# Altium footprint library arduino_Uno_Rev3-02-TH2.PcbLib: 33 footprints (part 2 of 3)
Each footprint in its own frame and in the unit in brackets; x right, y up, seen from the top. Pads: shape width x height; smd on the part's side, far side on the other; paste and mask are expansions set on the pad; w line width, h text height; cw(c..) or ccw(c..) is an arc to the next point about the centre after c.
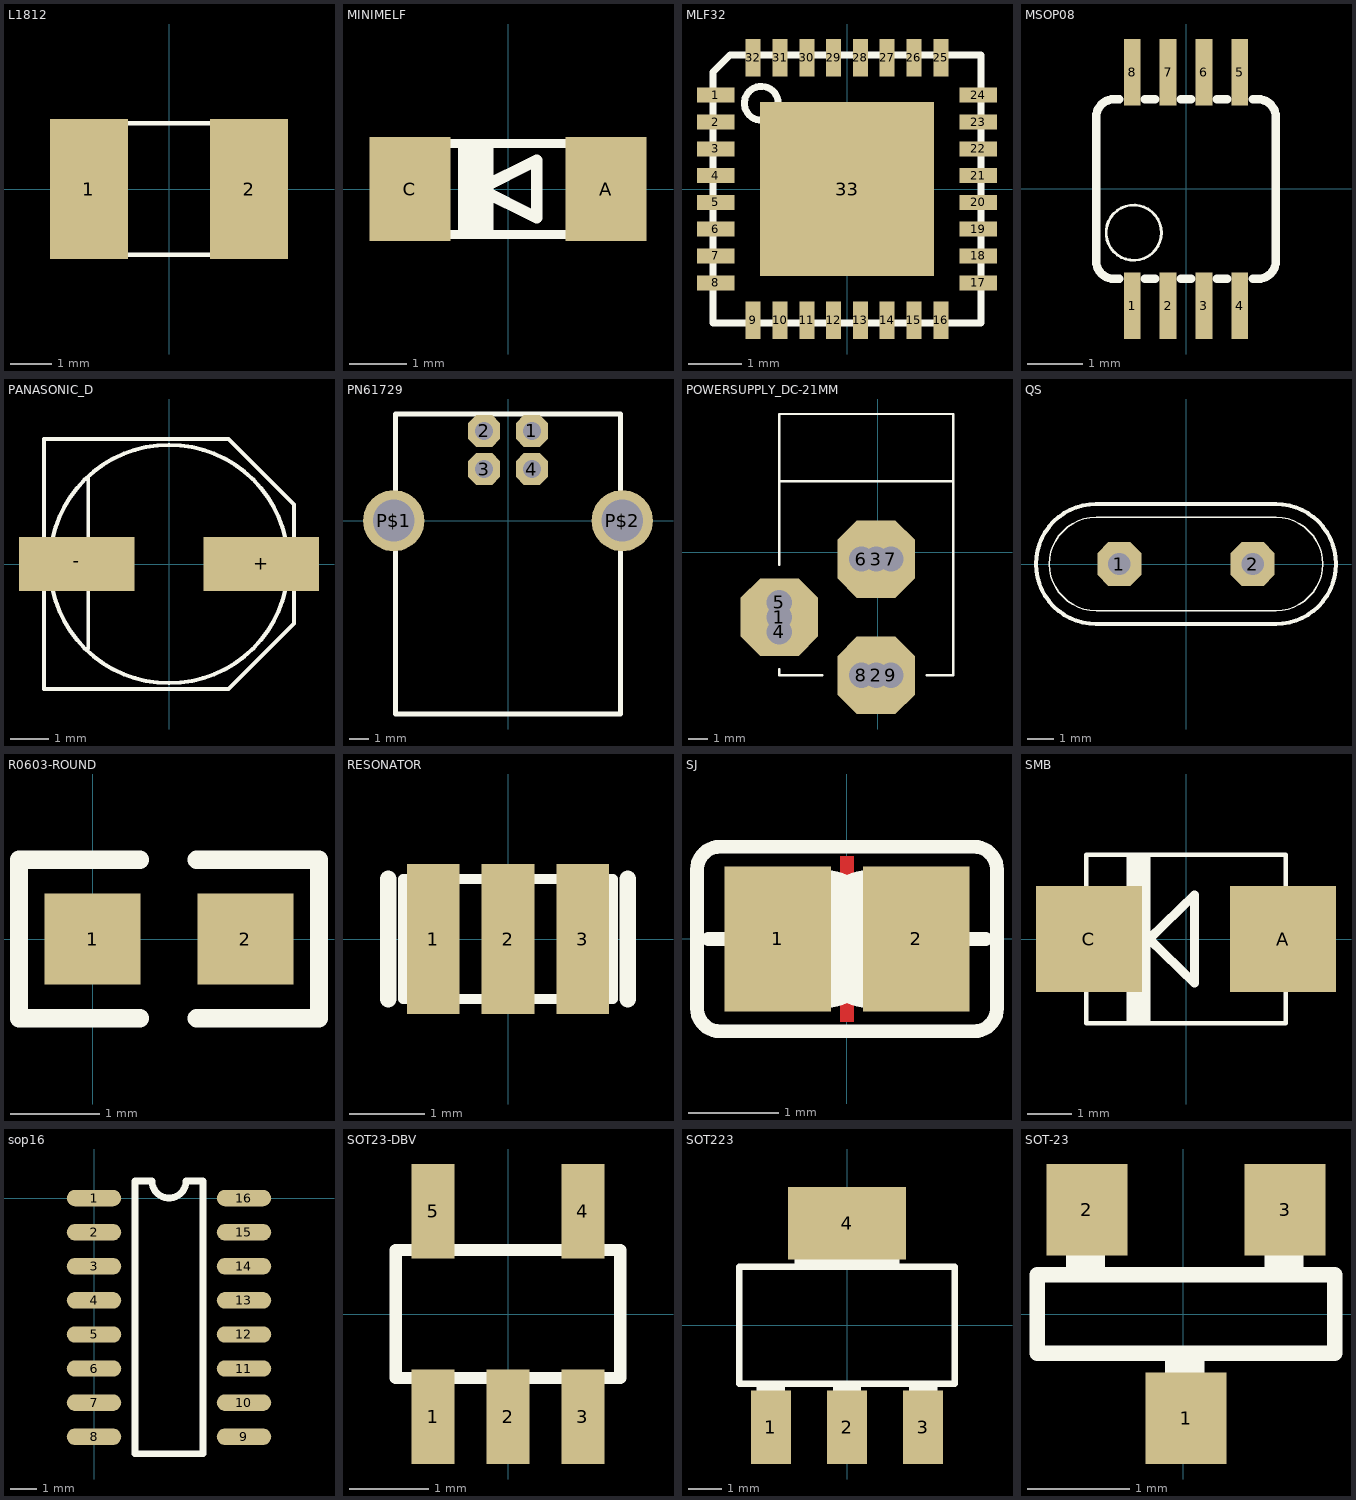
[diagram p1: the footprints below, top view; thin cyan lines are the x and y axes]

## L1812 [mm]
pads (2):
  rect 1.9x3.4 smd: 1(-1.95,0) 2(1.95,0)
Top Overlay:
  rectangle: -2.388,-1.651 -1.438,1.649
  rectangle: 1.448,-1.651 2.398,1.649
  lines w0.102: -1.473,1.6 1.473,1.6 ; -1.448,-1.6 1.473,-1.6

## MINIMELF [mm]
pads (2):
  rect 1.4x1.8 smd: A(1.7,0) C(-1.7,0)
Top Overlay:
  rectangle: -0.864,-0.787 -0.254,0.787
  rectangle: 1.295,-0.864 1.854,0.864
  rectangle: -1.854,-0.864 -1.295,0.864
  lines w0.152: -1.321,-0.787 1.321,-0.787 ; -1.321,0.787 1.321,0.787
  lines w0.203: -0.5,0 0.5,-0.5 0.5,0.5 -0.5,0

## MLF32 [mm]
pads (33):
  rect 0.7x0.28 smd: 1(-2.45,1.75) 2(-2.45,1.25) 3(-2.45,0.75) 4(-2.45,0.25) 5(-2.45,-0.25) 6(-2.45,-0.75) 7(-2.45,-1.25) 8(-2.45,-1.75) 17(2.45,-1.75) 18(2.45,-1.25) 19(2.45,-0.75) 20(2.45,-0.25) 21(2.45,0.25) 22(2.45,0.75) 23(2.45,1.25) 24(2.45,1.75)
  rect 0.28x0.7 smd: 9(-1.75,-2.45) 10(-1.25,-2.45) 11(-0.75,-2.45) 12(-0.25,-2.45) 13(0.25,-2.45) 14(0.75,-2.45) 15(1.25,-2.45) 16(1.75,-2.45) 25(1.75,2.45) 26(1.25,2.45) 27(0.75,2.45) 28(0.25,2.45) 29(-0.25,2.45) 30(-0.75,2.45) 31(-1.25,2.45) 32(-1.75,2.45)
  rect 3.254x3.254 smd: 33(0,0)
Top Layer:
  rectangle: -0.635,-0.635 0.635,0.635
Top Overlay:
  circle w0.127: c-1.6,1.6 r0.316
  lines w0.127: -2.5,-2.5 -2.5,2.183 -2.183,2.5 2.5,2.5 2.5,-2.5 -2.5,-2.5

## MSOP08 [mm]
pads (8):
  rect 0.3x1.2 smd: 1(-0.976,-2.113) 2(-0.326,-2.113) 3(0.324,-2.113) 4(0.974,-2.113) 5(0.974,2.112) 6(0.324,2.112) 7(-0.326,2.112) 8(-0.976,2.112)
Top Overlay:
  circle w0.051: c-0.946,-0.791 r0.5
  rectangle: -1.098,1.624 -0.854,2.356
  rectangle: -0.447,1.624 -0.204,2.356
  rectangle: 0.203,1.624 0.446,2.356
  rectangle: 0.853,1.624 1.096,2.356
  rectangle: -1.097,-2.357 -0.854,-1.625
  rectangle: -0.447,-2.357 -0.204,-1.626
  rectangle: 0.203,-2.357 0.446,-1.626
  rectangle: 0.853,-2.357 1.096,-1.626
  lines w0.152: -1.341,-1.626 -1.204,-1.626 ; -1.301,-1.626 cw(c-1.301,-1.301) -1.626,-1.301 -1.626,1.299 cw(c-1.301,1.299) -1.301,1.624 -1.204,1.624 ; -0.747,-1.626 -0.554,-1.626 ; -0.747,1.624 -0.554,1.624 ; -0.097,-1.626 0.096,-1.626 ; -0.097,1.624 0.096,1.624 ; 0.553,-1.626 0.746,-1.626 ; 0.553,1.624 0.746,1.624 ; 1.203,-1.626 1.299,-1.626 ccw(c1.299,-1.301) 1.624,-1.301 1.624,1.299 ccw(c1.299,1.299) 1.299,1.624 1.203,1.624

## PANASONIC_D [mm]
pads (2):
  rect 3x1.4 smd: +(2.4,0) -(-2.4,0)
Top Overlay:
  circle w0.102: c0,0 r3.1
  rectangle: -3.65,-0.35 -3.05,0.35
  rectangle: 3.05,-0.35 3.65,0.35
  lines w0.102: -3.25,-0.95 -3.25,-3.25 ; -3.25,0.95 -3.25,3.25 ; -2.95,-0.95 ccw(c0,0) 2.95,-0.95 ; -2.95,0.95 cw(c0,0) 2.95,0.95 ; -2.1,-2.2 -2.1,2.25 ; 3.25,-0.95 3.25,-1.55 ; 3.25,0.95 3.25,1.55 ; -3.25,-3.25 1.55,-3.25 ; -3.25,-3.25 -3.25,3.25 ; -3.25,-3.25 1.55,-3.25 ; -3.25,3.25 1.55,3.25 ; -3.25,3.25 1.55,3.25 ; 1.55,-3.25 3.25,-1.55 ; 1.55,-3.25 3.25,-1.55 ; 1.55,3.25 3.25,1.55 ; 1.55,3.25 3.25,1.55 ; 3.25,-1.55 3.25,1.55

## PN61729 [mil]
pads (6):
  oct 66x66 hole 37.4: 1(49.21,185.43) 2(-49.21,185.43) 3(-49.21,106.69) 4(49.21,106.69)
  round 126.61 hole 86.61: P$1(-236.22,0) P$2(236.22,0)
Top Overlay:
  lines w10: -232.28,-399.61 232.28,-399.61 232.28,220.47 -232.28,220.47 -232.28,-399.61

## POWERSUPPLY_DC-21MM [mm]
pads (9):
  oct 4x4 hole 1.3: 1(-5.08,-3.353) 2(-0.076,-6.35) 3(-0.076,-0.356)
  round 1.95 hole 1.3: 4(-5.08,-4.115) 5(-5.08,-2.591) 6(-0.838,-0.356) 7(0.686,-0.356) 8(-0.838,-6.35) 9(0.686,-6.35)
Top Overlay:
  lines w0.127: -5.08,-6.032 -5.08,-6.35 -2.857,-6.35 ; -5.08,-0.635 -5.08,7.137 3.912,7.137 3.912,3.658 ; -5.055,3.658 3.912,3.658 ; 2.54,-6.35 3.912,-6.35 3.912,3.658

## QS [mil]
pads (2):
  oct 66x66 hole 33.46: 1(-100,0) 2(100,0)
Top Overlay:
  lines w2: -135,-70 cw(c-135,0) -135,70 135,70 cw(c135,0) 135,-70 -135,-70
  lines w6: -135,-90 cw(c-135,0) -135,90 135,90 cw(c135,0) 135,-90 -135,-90

## R0603-ROUND [mil]
pads (2):
  rect 42.5x40 smd: 1(0,0) 2(67.5,0)
Top Overlay:
  lines w8: 21,-35 -32.5,-35 -32.5,35 21,35 ; 46,-35 100,-35 ; 46,35 100,35 100,-34

## RESONATOR [mm]
pads (3):
  rect 0.7x2 smd: 1(-1,0) 2(0,0) 3(1,0)
Top Overlay:
  lines w0.127: -1.4,-0.8 1.4,-0.8 1.4,0.8 -1.4,0.8 -1.4,-0.8
  lines w0.22: -1.6,-0.8 -1.6,0.8 ; 1.6,-0.8 1.6,0.8

## SJ [mil]
pads (2):
  rect 46x63 smd: 1(-30,0) 2(30,0)
Top Layer:
  rectangle: -3,-36 3,36
Top Overlay:
  lines w6: -60,0 -40,0 ; 40,0 60,0 ; -65,-30 ccw(c-55,-30) -55,-40 55,-40 ccw(c55,-30) 65,-30 65,30 ccw(c55,30) 55,40 -55,40 ccw(c-55,30) -65,30 -65,-30
  lines w50: -10,-5 cw(c-10,0) -10,5 ; 10,-5 ccw(c10,0) 10,5

## SMB [mm]
pads (2):
  rect 2.4x2.4 smd: A(2.2,0) C(-2.2,0)
Top Overlay:
  rectangle: -2.794,-1.092 -2.261,1.092
  rectangle: 2.261,-1.092 2.794,1.092
  rectangle: -1.35,-1.9 -0.8,1.9
  lines w0.102: -2.261,-1.905 2.261,-1.905 2.261,1.905 -2.261,1.905 -2.261,-1.905
  lines w0.203: -0.83,0 0.193,1 0.193,-1 -0.83,0

## sop16 [mil]
pads (16):
  oval 80x24 smd: 1(0,0) 2(0,-50) 3(0,-100) 4(0,-150) 5(0,-200) 6(0,-250) 7(0,-300) 8(0,-350) 9(220,-350) 10(220,-300) 11(220,-250) 12(220,-200) 13(220,-150) 14(220,-100) 15(220,-50) 16(220,0)
Top Overlay:
  lines w10: 60,-375 160,-375 160,25 135,25 cw(c110,25) 85,25 60,25 60,-375

## SOT23-DBV [mm]
pads (5):
  rect 0.55x1.2 smd: 1(-0.95,-1.3) 2(0,-1.3) 3(0.95,-1.3) 4(0.95,1.3) 5(-0.95,1.3)
Top Overlay:
  rectangle: -1.2,-1.5 -0.7,-0.85
  rectangle: -0.25,-1.5 0.25,-0.85
  rectangle: 0.7,-1.5 1.2,-0.85
  rectangle: 0.7,0.85 1.2,1.5
  rectangle: -1.2,0.85 -0.7,1.5
  lines w0.152: -1.328,-0.81 -1.422,-0.81 ; -1.328,0.81 -1.422,0.81 ; -0.522,-0.81 -0.428,-0.81 ; -0.522,0.81 0.522,0.81 ; 0.428,-0.81 0.522,-0.81 ; 1.328,-0.81 1.422,-0.81 ; 1.328,0.81 1.422,0.81 ; -1.422,-0.81 1.422,-0.81 ; -1.422,-0.81 -1.422,0.81 ; -1.422,0.81 1.422,0.81 ; 1.422,-0.81 1.422,0.81

## SOT223 [mil]
pads (4):
  rect 48x88 smd: 1(-91,-122) 2(0,-122) 3(91,-122)
  rect 141.73x86.61 smd: 4(0,122.01)
Top Overlay:
  rectangle: -63,71 63,144
  rectangle: -17,-144 17,-71
  rectangle: -108,-144 -74,-71
  rectangle: 74,-144 108,-71
  rectangle: -63,71 63,144
  rectangle: -17,-144 17,-71
  rectangle: -108,-144 -74,-71
  rectangle: 74,-144 108,-71
  lines w8: -129,-70 129,-70 129,70 -129,70 -129,-70

## SOT-23 [mil]
pads (3):
  rect 31x35 smd: 1(1,-40) 2(-37,40) 3(39,40)
Top Overlay:
  rectangle: 31,17 46,37
  rectangle: -45,17 -30,37
  rectangle: -7,-37 8,-17
  lines w6: -56,-15 58,-15 58,15 -56,15 -56,-15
